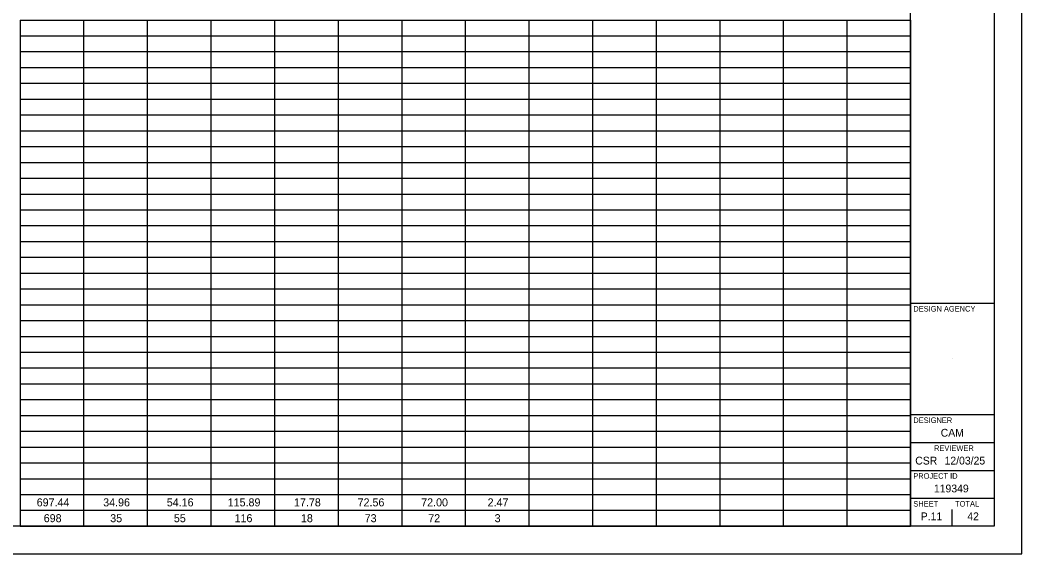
# Model space of a CAD drawing. Extents: x 0 to 34, y 0 to 22.
# Drawn here: x 16.02 to 34, y 0 to 9.58 of the extents above; entities that cross this region are included whole.
import ezdxf

# ---------------------------------------------------------------- set-up
doc = ezdxf.new("R2010")
doc.units = 0
for name, color, linetype in [('SH_Border', 7, 'Continuous'), ('SH_Cut_Line', 7, 'Continuous'), ('SH_Data', 7, 'Continuous'), ('SH_Text', 7, 'Continuous')]:
    doc.layers.add(name, color=color, linetype=linetype)

msp = doc.modelspace()

# ---------------------------------------------------------------- linework, layer by layer
at = {"layer": 'SH_Border'}
for p, q in [((32, 0.5), (32, 21.5)), ((32, 4.5), (33.5, 4.5)), ((32, 2.5), (33.5, 2.5)), ((32, 2), (33.5, 2)), ((32, 1.5), (33.5, 1.5)), ((32, 1), (33.5, 1))]:
    msp.add_line(p, q, dxfattribs=at)
msp.add_lwpolyline([(1.5, 21.5), (33.5, 21.5), (33.5, 0.5), (1.5, 0.5)], close=True, dxfattribs=at)
at = {"layer": 'SH_Cut_Line'}
msp.add_lwpolyline([(0, 0), (34, 0), (34, 22), (0, 22)], close=True, dxfattribs=at)
at = {"layer": 'SH_Data'}
for p, q in [((32.75, 3.5), (32.75, 3.5)), ((32.75, 0.5), (32.75, 0.8)), ((32.375, 0.675), (32.375, 0.675))]:
    msp.add_line(p, q, dxfattribs=at)
at = {"layer": 'SH_Text'}
for p, q in [((16.022, 9.581), (24.011, 9.581)), ((16.022, 9.581), (16.022, 9.297)), ((17.163, 9.581), (17.163, 9.297)), ((18.305, 9.581), (18.305, 9.297)), ((19.446, 9.581), (19.446, 9.297)), ((20.587, 9.581), (20.587, 9.297)), ((21.728, 9.581), (21.728, 9.297)), ((22.87, 9.581), (22.87, 9.297)), ((24.011, 9.581), (25.152, 9.581)), ((24.011, 9.581), (24.011, 9.297)), ((25.152, 9.581), (27.435, 9.581)), ((25.152, 9.581), (25.152, 9.297)), ((26.294, 9.581), (26.294, 9.297)), ((27.435, 9.581), (30.859, 9.581)), ((27.435, 9.581), (27.435, 9.297)), ((28.576, 9.581), (28.576, 9.297)), ((29.717, 9.581), (29.717, 9.297)), ((30.859, 9.581), (32, 9.581)), ((30.859, 9.581), (30.859, 9.297)), ((32, 9.581), (32, 9.297)), ((16.022, 9.297), (24.011, 9.297)), ((16.022, 9.297), (16.022, 9.014)), ((17.163, 9.297), (17.163, 9.014)), ((18.305, 9.297), (18.305, 9.014)), ((19.446, 9.297), (19.446, 9.014)), ((20.587, 9.297), (20.587, 9.014)), ((21.728, 9.297), (21.728, 9.014)), ((22.87, 9.297), (22.87, 9.014)), ((24.011, 9.297), (25.152, 9.297)), ((24.011, 9.297), (24.011, 9.014)), ((25.152, 9.297), (27.435, 9.297)), ((25.152, 9.297), (25.152, 9.014)), ((26.294, 9.297), (26.294, 9.014)), ((27.435, 9.297), (30.859, 9.297)), ((27.435, 9.297), (27.435, 9.014)), ((28.576, 9.297), (28.576, 9.014)), ((29.717, 9.297), (29.717, 9.014)), ((30.859, 9.297), (32, 9.297)), ((30.859, 9.297), (30.859, 9.014)), ((32, 9.297), (32, 9.014)), ((16.022, 9.014), (24.011, 9.014)), ((16.022, 9.014), (16.022, 8.73)), ((17.163, 9.014), (17.163, 8.73)), ((18.305, 9.014), (18.305, 8.73)), ((19.446, 9.014), (19.446, 8.73)), ((20.587, 9.014), (20.587, 8.73)), ((21.728, 9.014), (21.728, 8.73)), ((22.87, 9.014), (22.87, 8.73)), ((24.011, 9.014), (25.152, 9.014)), ((24.011, 9.014), (24.011, 8.73)), ((25.152, 9.014), (27.435, 9.014)), ((25.152, 9.014), (25.152, 8.73)), ((26.294, 9.014), (26.294, 8.73)), ((27.435, 9.014), (30.859, 9.014)), ((27.435, 9.014), (27.435, 8.73)), ((28.576, 9.014), (28.576, 8.73)), ((29.717, 9.014), (29.717, 8.73)), ((30.859, 9.014), (32, 9.014)), ((30.859, 9.014), (30.859, 8.73)), ((32, 9.014), (32, 8.73)), ((16.022, 8.73), (24.011, 8.73)), ((16.022, 8.73), (16.022, 8.446)), ((17.163, 8.73), (17.163, 8.446)), ((18.305, 8.73), (18.305, 8.446)), ((19.446, 8.73), (19.446, 8.446)), ((20.587, 8.73), (20.587, 8.446)), ((21.728, 8.73), (21.728, 8.446)), ((22.87, 8.73), (22.87, 8.446)), ((24.011, 8.73), (25.152, 8.73)), ((24.011, 8.73), (24.011, 8.446)), ((25.152, 8.73), (27.435, 8.73)), ((25.152, 8.73), (25.152, 8.446)), ((26.294, 8.73), (26.294, 8.446)), ((27.435, 8.73), (30.859, 8.73)), ((27.435, 8.73), (27.435, 8.446)), ((28.576, 8.73), (28.576, 8.446)), ((29.717, 8.73), (29.717, 8.446)), ((30.859, 8.73), (32, 8.73)), ((30.859, 8.73), (30.859, 8.446)), ((32, 8.73), (32, 8.446)), ((16.022, 8.446), (24.011, 8.446)), ((16.022, 8.446), (16.022, 8.162)), ((17.163, 8.446), (17.163, 8.162)), ((18.305, 8.446), (18.305, 8.162)), ((19.446, 8.446), (19.446, 8.162)), ((20.587, 8.446), (20.587, 8.162)), ((21.728, 8.446), (21.728, 8.162)), ((22.87, 8.446), (22.87, 8.162)), ((24.011, 8.446), (25.152, 8.446)), ((24.011, 8.446), (24.011, 8.162)), ((25.152, 8.446), (27.435, 8.446)), ((25.152, 8.446), (25.152, 8.162)), ((26.294, 8.446), (26.294, 8.162)), ((27.435, 8.446), (30.859, 8.446)), ((27.435, 8.446), (27.435, 8.162)), ((28.576, 8.446), (28.576, 8.162)), ((29.717, 8.446), (29.717, 8.162)), ((30.859, 8.446), (32, 8.446)), ((30.859, 8.446), (30.859, 8.162)), ((32, 8.446), (32, 8.162)), ((16.022, 8.162), (24.011, 8.162)), ((16.022, 8.162), (16.022, 7.878)), ((17.163, 8.162), (17.163, 7.878)), ((18.305, 8.162), (18.305, 7.878)), ((19.446, 8.162), (19.446, 7.878)), ((20.587, 8.162), (20.587, 7.878)), ((21.728, 8.162), (21.728, 7.878)), ((22.87, 8.162), (22.87, 7.878)), ((24.011, 8.162), (25.152, 8.162)), ((24.011, 8.162), (24.011, 7.878)), ((25.152, 8.162), (27.435, 8.162)), ((25.152, 8.162), (25.152, 7.878)), ((26.294, 8.162), (26.294, 7.878)), ((27.435, 8.162), (30.859, 8.162)), ((27.435, 8.162), (27.435, 7.878)), ((28.576, 8.162), (28.576, 7.878)), ((29.717, 8.162), (29.717, 7.878)), ((30.859, 8.162), (32, 8.162)), ((30.859, 8.162), (30.859, 7.878)), ((32, 8.162), (32, 7.878)), ((16.022, 7.878), (24.011, 7.878)), ((16.022, 7.878), (16.022, 7.595)), ((17.163, 7.878), (17.163, 7.595)), ((18.305, 7.878), (18.305, 7.595)), ((19.446, 7.878), (19.446, 7.595)), ((20.587, 7.878), (20.587, 7.595)), ((21.728, 7.878), (21.728, 7.595)), ((22.87, 7.878), (22.87, 7.595)), ((24.011, 7.878), (25.152, 7.878)), ((24.011, 7.878), (24.011, 7.595)), ((25.152, 7.878), (27.435, 7.878)), ((25.152, 7.878), (25.152, 7.595)), ((26.294, 7.878), (26.294, 7.595)), ((27.435, 7.878), (30.859, 7.878)), ((27.435, 7.878), (27.435, 7.595)), ((28.576, 7.878), (28.576, 7.595)), ((29.717, 7.878), (29.717, 7.595)), ((30.859, 7.878), (32, 7.878)), ((30.859, 7.878), (30.859, 7.595)), ((32, 7.878), (32, 7.595)), ((16.022, 7.595), (24.011, 7.595)), ((16.022, 7.595), (16.022, 7.311)), ((17.163, 7.595), (17.163, 7.311)), ((18.305, 7.595), (18.305, 7.311)), ((19.446, 7.595), (19.446, 7.311)), ((20.587, 7.595), (20.587, 7.311)), ((21.728, 7.595), (21.728, 7.311)), ((22.87, 7.595), (22.87, 7.311)), ((24.011, 7.595), (25.152, 7.595)), ((24.011, 7.595), (24.011, 7.311)), ((25.152, 7.595), (27.435, 7.595)), ((25.152, 7.595), (25.152, 7.311)), ((26.294, 7.595), (26.294, 7.311)), ((27.435, 7.595), (30.859, 7.595)), ((27.435, 7.595), (27.435, 7.311)), ((28.576, 7.595), (28.576, 7.311)), ((29.717, 7.595), (29.717, 7.311)), ((30.859, 7.595), (32, 7.595)), ((30.859, 7.595), (30.859, 7.311)), ((32, 7.595), (32, 7.311)), ((16.022, 7.311), (24.011, 7.311)), ((16.022, 7.311), (16.022, 7.027)), ((17.163, 7.311), (17.163, 7.027)), ((18.305, 7.311), (18.305, 7.027)), ((19.446, 7.311), (19.446, 7.027)), ((20.587, 7.311), (20.587, 7.027)), ((21.728, 7.311), (21.728, 7.027)), ((22.87, 7.311), (22.87, 7.027)), ((24.011, 7.311), (25.152, 7.311)), ((24.011, 7.311), (24.011, 7.027)), ((25.152, 7.311), (27.435, 7.311)), ((25.152, 7.311), (25.152, 7.027)), ((26.294, 7.311), (26.294, 7.027)), ((27.435, 7.311), (30.859, 7.311)), ((27.435, 7.311), (27.435, 7.027)), ((28.576, 7.311), (28.576, 7.027)), ((29.717, 7.311), (29.717, 7.027)), ((30.859, 7.311), (32, 7.311)), ((30.859, 7.311), (30.859, 7.027)), ((32, 7.311), (32, 7.027)), ((16.022, 7.027), (24.011, 7.027)), ((16.022, 7.027), (16.022, 6.743)), ((17.163, 7.027), (17.163, 6.743)), ((18.305, 7.027), (18.305, 6.743)), ((19.446, 7.027), (19.446, 6.743)), ((20.587, 7.027), (20.587, 6.743)), ((21.728, 7.027), (21.728, 6.743)), ((22.87, 7.027), (22.87, 6.743)), ((24.011, 7.027), (25.152, 7.027)), ((24.011, 7.027), (24.011, 6.743)), ((25.152, 7.027), (27.435, 7.027)), ((25.152, 7.027), (25.152, 6.743)), ((26.294, 7.027), (26.294, 6.743)), ((27.435, 7.027), (30.859, 7.027)), ((27.435, 7.027), (27.435, 6.743)), ((28.576, 7.027), (28.576, 6.743)), ((29.717, 7.027), (29.717, 6.743)), ((30.859, 7.027), (32, 7.027)), ((30.859, 7.027), (30.859, 6.743)), ((32, 7.027), (32, 6.743)), ((16.022, 6.743), (24.011, 6.743)), ((16.022, 6.743), (16.022, 6.459)), ((17.163, 6.743), (17.163, 6.459)), ((18.305, 6.743), (18.305, 6.459)), ((19.446, 6.743), (19.446, 6.459)), ((20.587, 6.743), (20.587, 6.459)), ((21.728, 6.743), (21.728, 6.459)), ((22.87, 6.743), (22.87, 6.459)), ((24.011, 6.743), (25.152, 6.743)), ((24.011, 6.743), (24.011, 6.459)), ((25.152, 6.743), (27.435, 6.743)), ((25.152, 6.743), (25.152, 6.459)), ((26.294, 6.743), (26.294, 6.459)), ((27.435, 6.743), (30.859, 6.743)), ((27.435, 6.743), (27.435, 6.459)), ((28.576, 6.743), (28.576, 6.459)), ((29.717, 6.743), (29.717, 6.459)), ((30.859, 6.743), (32, 6.743)), ((30.859, 6.743), (30.859, 6.459)), ((32, 6.743), (32, 6.459)), ((16.022, 6.459), (24.011, 6.459)), ((16.022, 6.459), (16.022, 6.176)), ((17.163, 6.459), (17.163, 6.176)), ((18.305, 6.459), (18.305, 6.176)), ((19.446, 6.459), (19.446, 6.176)), ((20.587, 6.459), (20.587, 6.176)), ((21.728, 6.459), (21.728, 6.176)), ((22.87, 6.459), (22.87, 6.176)), ((24.011, 6.459), (25.152, 6.459)), ((24.011, 6.459), (24.011, 6.176)), ((25.152, 6.459), (27.435, 6.459)), ((25.152, 6.459), (25.152, 6.176)), ((26.294, 6.459), (26.294, 6.176)), ((27.435, 6.459), (30.859, 6.459)), ((27.435, 6.459), (27.435, 6.176)), ((28.576, 6.459), (28.576, 6.176)), ((29.717, 6.459), (29.717, 6.176)), ((30.859, 6.459), (32, 6.459)), ((30.859, 6.459), (30.859, 6.176)), ((32, 6.459), (32, 6.176)), ((16.022, 6.176), (24.011, 6.176)), ((16.022, 6.176), (16.022, 5.892)), ((17.163, 6.176), (17.163, 5.892)), ((18.305, 6.176), (18.305, 5.892)), ((19.446, 6.176), (19.446, 5.892)), ((20.587, 6.176), (20.587, 5.892)), ((21.728, 6.176), (21.728, 5.892)), ((22.87, 6.176), (22.87, 5.892)), ((24.011, 6.176), (25.152, 6.176)), ((24.011, 6.176), (24.011, 5.892)), ((25.152, 6.176), (27.435, 6.176)), ((25.152, 6.176), (25.152, 5.892)), ((26.294, 6.176), (26.294, 5.892)), ((27.435, 6.176), (30.859, 6.176)), ((27.435, 6.176), (27.435, 5.892)), ((28.576, 6.176), (28.576, 5.892)), ((29.717, 6.176), (29.717, 5.892)), ((30.859, 6.176), (32, 6.176)), ((30.859, 6.176), (30.859, 5.892)), ((32, 6.176), (32, 5.892)), ((16.022, 5.892), (24.011, 5.892)), ((16.022, 5.892), (16.022, 5.608)), ((17.163, 5.892), (17.163, 5.608)), ((18.305, 5.892), (18.305, 5.608)), ((19.446, 5.892), (19.446, 5.608)), ((20.587, 5.892), (20.587, 5.608)), ((21.728, 5.892), (21.728, 5.608)), ((22.87, 5.892), (22.87, 5.608)), ((24.011, 5.892), (25.152, 5.892)), ((24.011, 5.892), (24.011, 5.608)), ((25.152, 5.892), (27.435, 5.892)), ((25.152, 5.892), (25.152, 5.608)), ((26.294, 5.892), (26.294, 5.608)), ((27.435, 5.892), (30.859, 5.892)), ((27.435, 5.892), (27.435, 5.608)), ((28.576, 5.892), (28.576, 5.608)), ((29.717, 5.892), (29.717, 5.608)), ((30.859, 5.892), (32, 5.892)), ((30.859, 5.892), (30.859, 5.608)), ((32, 5.892), (32, 5.608)), ((16.022, 5.608), (24.011, 5.608)), ((16.022, 5.608), (16.022, 5.324)), ((17.163, 5.608), (17.163, 5.324)), ((18.305, 5.608), (18.305, 5.324)), ((19.446, 5.608), (19.446, 5.324)), ((20.587, 5.608), (20.587, 5.324)), ((21.728, 5.608), (21.728, 5.324)), ((22.87, 5.608), (22.87, 5.324)), ((24.011, 5.608), (25.152, 5.608)), ((24.011, 5.608), (24.011, 5.324)), ((25.152, 5.608), (27.435, 5.608)), ((25.152, 5.608), (25.152, 5.324)), ((26.294, 5.608), (26.294, 5.324)), ((27.435, 5.608), (30.859, 5.608)), ((27.435, 5.608), (27.435, 5.324)), ((28.576, 5.608), (28.576, 5.324)), ((29.717, 5.608), (29.717, 5.324)), ((30.859, 5.608), (32, 5.608)), ((30.859, 5.608), (30.859, 5.324)), ((32, 5.608), (32, 5.324)), ((16.022, 5.324), (24.011, 5.324)), ((16.022, 5.324), (16.022, 4.757)), ((17.163, 5.324), (17.163, 4.757)), ((18.305, 5.324), (18.305, 4.757)), ((19.446, 5.324), (19.446, 4.757)), ((20.587, 5.324), (20.587, 4.757)), ((21.728, 5.324), (21.728, 4.757)), ((22.87, 5.324), (22.87, 4.757)), ((24.011, 5.324), (25.152, 5.324)), ((24.011, 5.324), (24.011, 4.757)), ((25.152, 5.324), (27.435, 5.324)), ((25.152, 5.324), (25.152, 4.757)), ((26.294, 5.324), (26.294, 4.757)), ((27.435, 5.324), (30.859, 5.324)), ((27.435, 5.324), (27.435, 4.757)), ((28.576, 5.324), (28.576, 4.757)), ((29.717, 5.324), (29.717, 4.757)), ((30.859, 5.324), (32, 5.324)), ((30.859, 5.324), (30.859, 4.757)), ((32, 5.324), (32, 4.757)), ((16.022, 5.041), (24.011, 5.041)), ((24.011, 5.041), (25.152, 5.041)), ((25.152, 5.041), (27.435, 5.041)), ((27.435, 5.041), (30.859, 5.041)), ((30.859, 5.041), (32, 5.041)), ((16.022, 4.757), (24.011, 4.757)), ((16.022, 4.757), (16.022, 4.473)), ((17.163, 4.757), (17.163, 4.473)), ((18.305, 4.757), (18.305, 4.473)), ((19.446, 4.757), (19.446, 4.473)), ((20.587, 4.757), (20.587, 4.473)), ((21.728, 4.757), (21.728, 4.473)), ((22.87, 4.757), (22.87, 4.473)), ((24.011, 4.757), (25.152, 4.757)), ((24.011, 4.757), (24.011, 4.473)), ((25.152, 4.757), (27.435, 4.757)), ((25.152, 4.757), (25.152, 4.473)), ((26.294, 4.757), (26.294, 4.473)), ((27.435, 4.757), (30.859, 4.757)), ((27.435, 4.757), (27.435, 4.473)), ((28.576, 4.757), (28.576, 4.473)), ((29.717, 4.757), (29.717, 4.473)), ((30.859, 4.757), (32, 4.757)), ((30.859, 4.757), (30.859, 4.473)), ((32, 4.757), (32, 4.473)), ((16.022, 4.473), (24.011, 4.473)), ((16.022, 4.473), (16.022, 4.189)), ((17.163, 4.473), (17.163, 4.189)), ((18.305, 4.473), (18.305, 4.189)), ((19.446, 4.473), (19.446, 4.189)), ((20.587, 4.473), (20.587, 4.189)), ((21.728, 4.473), (21.728, 4.189)), ((22.87, 4.473), (22.87, 4.189)), ((24.011, 4.473), (25.152, 4.473)), ((24.011, 4.473), (24.011, 4.189)), ((25.152, 4.473), (27.435, 4.473)), ((25.152, 4.473), (25.152, 4.189)), ((26.294, 4.473), (26.294, 4.189)), ((27.435, 4.473), (30.859, 4.473)), ((27.435, 4.473), (27.435, 4.189)), ((28.576, 4.473), (28.576, 4.189)), ((29.717, 4.473), (29.717, 4.189)), ((30.859, 4.473), (32, 4.473)), ((30.859, 4.473), (30.859, 4.189)), ((32, 4.473), (32, 4.189)), ((16.022, 4.189), (24.011, 4.189)), ((16.022, 4.189), (16.022, 3.905)), ((17.163, 4.189), (17.163, 3.905)), ((18.305, 4.189), (18.305, 3.905)), ((19.446, 4.189), (19.446, 3.905)), ((20.587, 4.189), (20.587, 3.905)), ((21.728, 4.189), (21.728, 3.905)), ((22.87, 4.189), (22.87, 3.905)), ((24.011, 4.189), (25.152, 4.189)), ((24.011, 4.189), (24.011, 3.905)), ((25.152, 4.189), (27.435, 4.189)), ((25.152, 4.189), (25.152, 3.905)), ((26.294, 4.189), (26.294, 3.905)), ((27.435, 4.189), (30.859, 4.189)), ((27.435, 4.189), (27.435, 3.905)), ((28.576, 4.189), (28.576, 3.905)), ((29.717, 4.189), (29.717, 3.905)), ((30.859, 4.189), (32, 4.189)), ((30.859, 4.189), (30.859, 3.905)), ((32, 4.189), (32, 3.905)), ((16.022, 3.905), (24.011, 3.905)), ((16.022, 3.905), (16.022, 3.338)), ((17.163, 3.905), (17.163, 3.338)), ((18.305, 3.905), (18.305, 3.338)), ((19.446, 3.905), (19.446, 3.338)), ((20.587, 3.905), (20.587, 3.338)), ((21.728, 3.905), (21.728, 3.338)), ((22.87, 3.905), (22.87, 3.338)), ((24.011, 3.905), (25.152, 3.905)), ((24.011, 3.905), (24.011, 3.338)), ((25.152, 3.905), (27.435, 3.905)), ((25.152, 3.905), (25.152, 3.338)), ((26.294, 3.905), (26.294, 3.338)), ((27.435, 3.905), (30.859, 3.905)), ((27.435, 3.905), (27.435, 3.338)), ((28.576, 3.905), (28.576, 3.338)), ((29.717, 3.905), (29.717, 3.338)), ((30.859, 3.905), (32, 3.905)), ((30.859, 3.905), (30.859, 3.338)), ((32, 3.905), (32, 3.338)), ((16.022, 3.622), (24.011, 3.622)), ((24.011, 3.622), (25.152, 3.622)), ((25.152, 3.622), (27.435, 3.622)), ((27.435, 3.622), (30.859, 3.622)), ((30.859, 3.622), (32, 3.622)), ((16.022, 3.338), (24.011, 3.338)), ((16.022, 3.338), (16.022, 3.054)), ((17.163, 3.338), (17.163, 3.054)), ((18.305, 3.338), (18.305, 3.054)), ((19.446, 3.338), (19.446, 3.054)), ((20.587, 3.338), (20.587, 3.054)), ((21.728, 3.338), (21.728, 3.054)), ((22.87, 3.338), (22.87, 3.054)), ((24.011, 3.338), (25.152, 3.338)), ((24.011, 3.338), (24.011, 3.054)), ((25.152, 3.338), (27.435, 3.338)), ((25.152, 3.338), (25.152, 3.054)), ((26.294, 3.338), (26.294, 3.054)), ((27.435, 3.338), (30.859, 3.338)), ((27.435, 3.338), (27.435, 3.054)), ((28.576, 3.338), (28.576, 3.054)), ((29.717, 3.338), (29.717, 3.054)), ((30.859, 3.338), (32, 3.338)), ((30.859, 3.338), (30.859, 3.054)), ((32, 3.338), (32, 3.054)), ((16.022, 3.054), (24.011, 3.054)), ((16.022, 3.054), (16.022, 2.77)), ((17.163, 3.054), (17.163, 2.77)), ((18.305, 3.054), (18.305, 2.77)), ((19.446, 3.054), (19.446, 2.77)), ((20.587, 3.054), (20.587, 2.77)), ((21.728, 3.054), (21.728, 2.77)), ((22.87, 3.054), (22.87, 2.77)), ((24.011, 3.054), (25.152, 3.054)), ((24.011, 3.054), (24.011, 2.77)), ((25.152, 3.054), (27.435, 3.054)), ((25.152, 3.054), (25.152, 2.77)), ((26.294, 3.054), (26.294, 2.77)), ((27.435, 3.054), (30.859, 3.054)), ((27.435, 3.054), (27.435, 2.77)), ((28.576, 3.054), (28.576, 2.77)), ((29.717, 3.054), (29.717, 2.77)), ((30.859, 3.054), (32, 3.054)), ((30.859, 3.054), (30.859, 2.77)), ((32, 3.054), (32, 2.77)), ((16.022, 2.77), (24.011, 2.77)), ((16.022, 2.77), (16.022, 2.486)), ((17.163, 2.77), (17.163, 2.486)), ((18.305, 2.77), (18.305, 2.486)), ((19.446, 2.77), (19.446, 2.486)), ((20.587, 2.77), (20.587, 2.486)), ((21.728, 2.77), (21.728, 2.486)), ((22.87, 2.77), (22.87, 2.486)), ((24.011, 2.77), (25.152, 2.77)), ((24.011, 2.77), (24.011, 2.486)), ((25.152, 2.77), (27.435, 2.77)), ((25.152, 2.77), (25.152, 2.486)), ((26.294, 2.77), (26.294, 2.486)), ((27.435, 2.77), (30.859, 2.77)), ((27.435, 2.77), (27.435, 2.486)), ((28.576, 2.77), (28.576, 2.486)), ((29.717, 2.77), (29.717, 2.486)), ((30.859, 2.77), (32, 2.77)), ((30.859, 2.77), (30.859, 2.486)), ((32, 2.77), (32, 2.486)), ((16.022, 2.486), (24.011, 2.486)), ((16.022, 2.486), (16.022, 1.919)), ((17.163, 2.486), (17.163, 1.919)), ((18.305, 2.486), (18.305, 1.919)), ((19.446, 2.486), (19.446, 1.919)), ((20.587, 2.486), (20.587, 1.919)), ((21.728, 2.486), (21.728, 1.919)), ((22.87, 2.486), (22.87, 1.919)), ((24.011, 2.486), (25.152, 2.486)), ((24.011, 2.486), (24.011, 1.919)), ((25.152, 2.486), (27.435, 2.486)), ((25.152, 2.486), (25.152, 1.919)), ((26.294, 2.486), (26.294, 1.919)), ((27.435, 2.486), (30.859, 2.486)), ((27.435, 2.486), (27.435, 1.919)), ((28.576, 2.486), (28.576, 1.919)), ((29.717, 2.486), (29.717, 1.919)), ((30.859, 2.486), (32, 2.486)), ((30.859, 2.486), (30.859, 1.919)), ((32, 2.486), (32, 1.919)), ((16.022, 2.203), (24.011, 2.203)), ((24.011, 2.203), (25.152, 2.203)), ((25.152, 2.203), (27.435, 2.203)), ((27.435, 2.203), (30.859, 2.203)), ((30.859, 2.203), (32, 2.203)), ((16.022, 1.919), (24.011, 1.919)), ((16.022, 1.919), (16.022, 1.635)), ((17.163, 1.919), (17.163, 1.635)), ((18.305, 1.919), (18.305, 1.635)), ((19.446, 1.919), (19.446, 1.635)), ((20.587, 1.919), (20.587, 1.635)), ((21.728, 1.919), (21.728, 1.635)), ((22.87, 1.919), (22.87, 1.635)), ((24.011, 1.919), (25.152, 1.919)), ((24.011, 1.919), (24.011, 1.635)), ((25.152, 1.919), (27.435, 1.919)), ((25.152, 1.919), (25.152, 1.635)), ((26.294, 1.919), (26.294, 1.635)), ((27.435, 1.919), (30.859, 1.919)), ((27.435, 1.919), (27.435, 1.635)), ((28.576, 1.919), (28.576, 1.635)), ((29.717, 1.919), (29.717, 1.635)), ((30.859, 1.919), (32, 1.919)), ((30.859, 1.919), (30.859, 1.635)), ((32, 1.919), (32, 1.635)), ((16.022, 1.635), (24.011, 1.635)), ((16.022, 1.635), (16.022, 1.351)), ((17.163, 1.635), (17.163, 1.351)), ((18.305, 1.635), (18.305, 1.351)), ((19.446, 1.635), (19.446, 1.351)), ((20.587, 1.635), (20.587, 1.351)), ((21.728, 1.635), (21.728, 1.351)), ((22.87, 1.635), (22.87, 1.351)), ((24.011, 1.635), (25.152, 1.635)), ((24.011, 1.635), (24.011, 1.351)), ((25.152, 1.635), (27.435, 1.635)), ((25.152, 1.635), (25.152, 1.351)), ((26.294, 1.635), (26.294, 1.351)), ((27.435, 1.635), (30.859, 1.635)), ((27.435, 1.635), (27.435, 1.351)), ((28.576, 1.635), (28.576, 1.351)), ((29.717, 1.635), (29.717, 1.351)), ((30.859, 1.635), (32, 1.635)), ((30.859, 1.635), (30.859, 1.351)), ((32, 1.635), (32, 1.351)), ((16.022, 1.351), (24.011, 1.351)), ((16.022, 1.351), (16.022, 1.068)), ((17.163, 1.351), (17.163, 1.068)), ((18.305, 1.351), (18.305, 1.068)), ((19.446, 1.351), (19.446, 1.068)), ((20.587, 1.351), (20.587, 1.068)), ((21.728, 1.351), (21.728, 1.068)), ((22.87, 1.351), (22.87, 1.068)), ((24.011, 1.351), (25.152, 1.351)), ((24.011, 1.351), (24.011, 1.068)), ((25.152, 1.351), (27.435, 1.351)), ((25.152, 1.351), (25.152, 1.068)), ((26.294, 1.351), (26.294, 1.068)), ((27.435, 1.351), (30.859, 1.351)), ((27.435, 1.351), (27.435, 1.068)), ((28.576, 1.351), (28.576, 1.068)), ((29.717, 1.351), (29.717, 1.068)), ((30.859, 1.351), (32, 1.351)), ((30.859, 1.351), (30.859, 1.068)), ((32, 1.351), (32, 1.068)), ((16.022, 1.068), (24.011, 1.068)), ((16.022, 1.068), (16.022, 0.5)), ((17.163, 1.068), (17.163, 0.5)), ((18.305, 1.068), (18.305, 0.5)), ((19.446, 1.068), (19.446, 0.5)), ((20.587, 1.068), (20.587, 0.5)), ((21.728, 1.068), (21.728, 0.5)), ((22.87, 1.068), (22.87, 0.5)), ((24.011, 1.068), (25.152, 1.068)), ((24.011, 1.068), (24.011, 0.5)), ((25.152, 1.068), (27.435, 1.068)), ((25.152, 1.068), (25.152, 0.5)), ((26.294, 1.068), (26.294, 0.5)), ((27.435, 1.068), (30.859, 1.068)), ((27.435, 1.068), (27.435, 0.5)), ((28.576, 1.068), (28.576, 0.5)), ((29.717, 1.068), (29.717, 0.5)), ((30.859, 1.068), (32, 1.068)), ((30.859, 1.068), (30.859, 0.5)), ((32, 1.068), (32, 0.5)), ((16.022, 0.784), (24.011, 0.784)), ((24.011, 0.784), (25.152, 0.784)), ((25.152, 0.784), (27.435, 0.784)), ((27.435, 0.784), (30.859, 0.784)), ((30.859, 0.784), (32, 0.784)), ((16.022, 0.5), (24.011, 0.5)), ((24.011, 0.5), (25.152, 0.5)), ((25.152, 0.5), (27.435, 0.5)), ((27.435, 0.5), (30.859, 0.5)), ((30.859, 0.5), (32, 0.5))]:
    msp.add_line(p, q, dxfattribs=at)

# ---------------------------------------------------------------- texts
at = {"layer": 'SH_Data'}
for s, height, p in [('DESIGN AGENCY', 0.1, (32.05, 4.35)), ('DESIGNER', 0.1, (32.05, 2.35)), ('CAM', 0.14, (32.542, 2.105)), ('REVIEWER', 0.1, (32.422, 1.85)), ('CSR', 0.14, (32.085, 1.605)), ('12/03/25', 0.14, (32.611, 1.605)), ('PROJECT ID', 0.1, (32.05, 1.35)), ('119349', 0.14, (32.42, 1.105)), ('SHEET', 0.1, (32.05, 0.85)), ('TOTAL', 0.1, (32.8, 0.85)), ('P.11', 0.14, (32.184, 0.605)), ('42', 0.14, (33.019, 0.605))]:
    msp.add_text(s, height=height, dxfattribs=at).set_placement(p)
at = {"layer": 'SH_Text'}
for s, height, p in [('697.44', 0.1436, (16.321, 0.854)), ('34.96', 0.1436, (17.514, 0.854)), ('54.16', 0.1436, (18.655, 0.854)), ('115.89', 0.1436, (19.748, 0.854)), ('17.78', 0.1436, (20.938, 0.854)), ('72.56', 0.1436, (22.079, 0.854)), ('72.00', 0.1436, (23.22, 0.854)), ('2.47', 0.1436, (24.412, 0.854)), ('698', 0.1436, (16.447, 0.57)), ('35', 0.1436, (17.64, 0.57)), ('55', 0.1436, (18.782, 0.57)), ('116', 0.1436, (19.871, 0.57)), ('18', 0.1436, (21.062, 0.57)), ('73', 0.1436, (22.206, 0.57)), ('72', 0.1436, (23.347, 0.57)), ('3', 0.144, (24.538, 0.57))]:
    msp.add_text(s, height=height, dxfattribs=at).set_placement(p)

doc.saveas('drawing.dxf')
